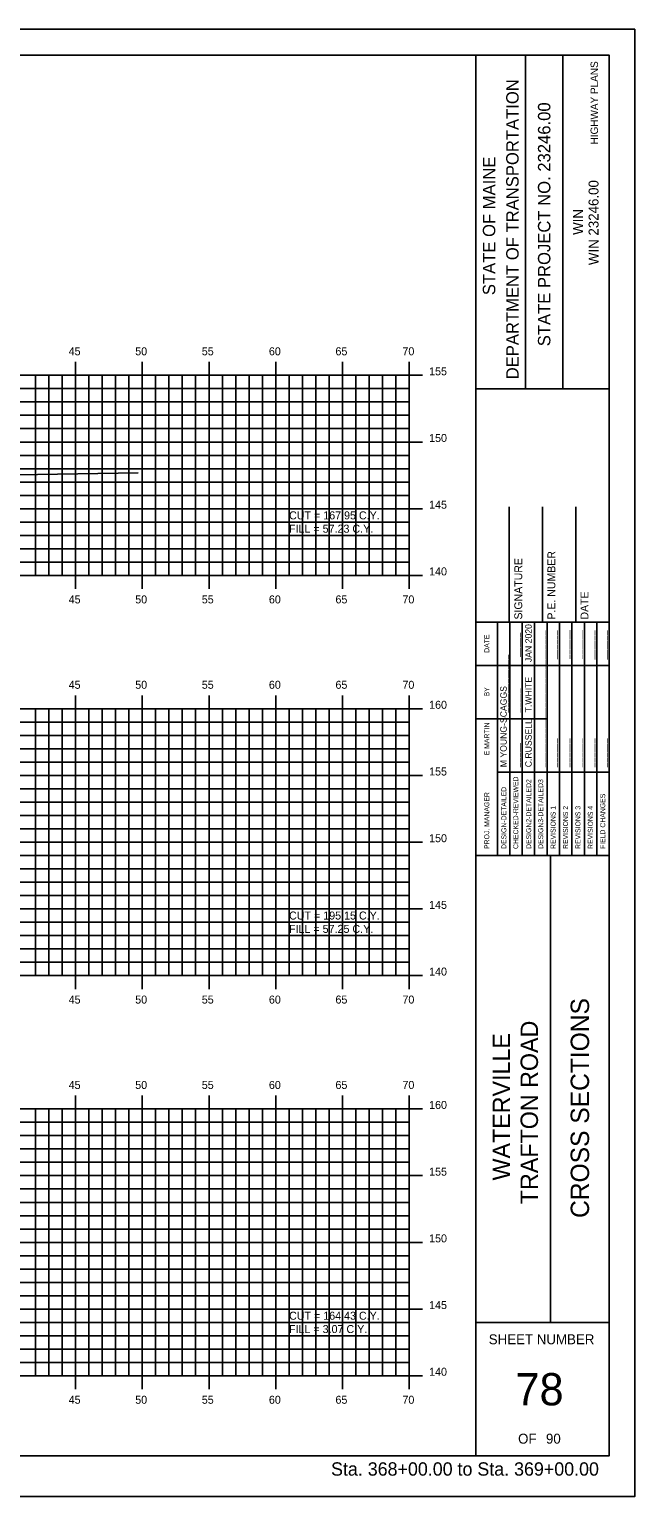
# Model space of a CAD drawing. Extents: x 1147855 to 1148025, y 608981 to 609091.
# Drawn here: x 1147979.7 to 1148025.1, y 608981.3 to 609091.3 of the extents above; entities that cross this region are included whole.
import ezdxf

# ---------------------------------------------------------------- set-up
doc = ezdxf.new("R2010")
doc.units = 0
for name, color, linetype in [('BORDER', 7, 'Continuous'), ('D_Text_Standard', 7, 'Continuous'), ('H_V ANNOTATION', 7, 'Continuous'), ('HIGHWAY_TITLE', 7, 'Continuous'), ('MAJOR', 7, 'Continuous'), ('MINOR', 7, 'Continuous'), ('PLOT BOUNDARY', 7, 'Continuous'), ('S_Roadway_Centerline', 7, 'Continuous')]:
    doc.layers.add(name, color=color, linetype=linetype)

msp = doc.modelspace()

# ---------------------------------------------------------------- linework, layer by layer
at = {"layer": 'BORDER'}
for p, q in [((1148013.21, 608984.34), (1148013.21, 609089.34)), ((1148016.94, 609064.33), (1148016.94, 609089.33)), ((1148019.73, 609064.33), (1148019.73, 609089.33)), ((1148013.21, 609064.33), (1148023.21, 609064.33)), ((1148015.71, 609046.84), (1148015.71, 609055.49)), ((1148018.21, 609046.84), (1148018.21, 609055.49)), ((1148020.71, 609046.84), (1148020.71, 609055.49)), ((1148013.21, 609046.84), (1148023.21, 609046.84)), ((1148013.21, 609029.34), (1148023.21, 609029.34)), ((1148018.8, 608994.34), (1148018.8, 609029.34)), ((1148013.21, 608994.34), (1148023.21, 608994.34))]:
    msp.add_line(p, q, dxfattribs=at)
msp.add_lwpolyline([(1147863.21, 608984.34), (1148023.21, 608984.34), (1148023.21, 609089.34), (1147863.21, 609089.34)], close=True, dxfattribs=at)
for points in [[(1148014.83, 609043.59), (1148014.83, 609046.84)], [(1148014.83, 609029.34), (1148014.83, 609046.13)], [(1148015.76, 609029.34), (1148015.76, 609046.84)], [(1148016.69, 609046.84), (1148016.69, 609029.34)], [(1148017.62, 609029.34), (1148017.62, 609046.84)], [(1148018.55, 609029.34), (1148018.55, 609046.84)], [(1148019.48, 609029.34), (1148019.48, 609046.84)], [(1148020.42, 609029.34), (1148020.42, 609046.84)], [(1148021.35, 609029.34), (1148021.35, 609046.84)], [(1148022.28, 609029.34), (1148022.28, 609046.84)], [(1148013.21, 609043.59), (1148023.21, 609043.59)], [(1148013.21, 609039.59), (1148014.83, 609039.59)], [(1148014.83, 609039.59), (1148018.55, 609039.59)], [(1148014.83, 609035.59), (1148023.21, 609035.59)]]:
    msp.add_lwpolyline(points, dxfattribs=at)
at = {"layer": 'MAJOR'}
for p, q in [((1147983.21, 609066.34), (1147983.21, 609065.34)), ((1147988.21, 609066.34), (1147988.21, 609065.34)), ((1147993.21, 609066.34), (1147993.21, 609065.34)), ((1147998.21, 609066.34), (1147998.21, 609065.34)), ((1148003.21, 609066.34), (1148003.21, 609065.34)), ((1148008.21, 609066.34), (1148008.21, 609065.34)), ((1147868.21, 609065.34), (1148008.21, 609065.34)), ((1147868.21, 609065.34), (1148008.21, 609065.34)), ((1147983.21, 609050.34), (1147983.21, 609065.34)), ((1147988.21, 609050.34), (1147988.21, 609065.34)), ((1147993.21, 609050.34), (1147993.21, 609065.34)), ((1147998.21, 609050.34), (1147998.21, 609065.34)), ((1148003.21, 609050.34), (1148003.21, 609065.34)), ((1148009.21, 609065.34), (1148007.21, 609065.34)), ((1148008.21, 609050.34), (1148008.21, 609065.34)), ((1148008.21, 609050.34), (1148008.21, 609065.34)), ((1147868.21, 609060.34), (1148008.21, 609060.34)), ((1148009.21, 609060.34), (1148007.21, 609060.34)), ((1147868.21, 609055.34), (1148008.21, 609055.34)), ((1148009.21, 609055.34), (1148007.21, 609055.34)), ((1147868.21, 609050.34), (1148008.21, 609050.34)), ((1147868.21, 609050.34), (1148008.21, 609050.34)), ((1147983.21, 609049.33), (1147983.21, 609050.34)), ((1147988.21, 609049.33), (1147988.21, 609050.34)), ((1147993.21, 609049.33), (1147993.21, 609050.34)), ((1147998.21, 609049.33), (1147998.21, 609050.34)), ((1148003.21, 609049.33), (1148003.21, 609050.34)), ((1148009.21, 609050.34), (1148007.21, 609050.34)), ((1148008.21, 609049.33), (1148008.21, 609050.34)), ((1147868.21, 609040.34), (1148008.21, 609040.34)), ((1147868.21, 609040.34), (1148008.21, 609040.34)), ((1147983.21, 609041.34), (1147983.21, 609040.34)), ((1147983.21, 609020.34), (1147983.21, 609040.34)), ((1147988.21, 609041.34), (1147988.21, 609040.34)), ((1147988.21, 609020.34), (1147988.21, 609040.34)), ((1147993.21, 609041.34), (1147993.21, 609040.34)), ((1147993.21, 609020.34), (1147993.21, 609040.34)), ((1147998.21, 609041.34), (1147998.21, 609040.34)), ((1147998.21, 609020.34), (1147998.21, 609040.34)), ((1148003.21, 609041.34), (1148003.21, 609040.34)), ((1148003.21, 609020.34), (1148003.21, 609040.34)), ((1148009.21, 609040.34), (1148007.21, 609040.34)), ((1148008.21, 609041.34), (1148008.21, 609040.34)), ((1148008.21, 609020.34), (1148008.21, 609040.34)), ((1148008.21, 609020.34), (1148008.21, 609040.34)), ((1147868.21, 609035.34), (1148008.21, 609035.34)), ((1148009.21, 609035.34), (1148007.21, 609035.34)), ((1147868.21, 609030.34), (1148008.21, 609030.34)), ((1148009.21, 609030.34), (1148007.21, 609030.34)), ((1147868.21, 609025.34), (1148008.21, 609025.34)), ((1148009.21, 609025.34), (1148007.21, 609025.34)), ((1147868.21, 609020.34), (1148008.21, 609020.34)), ((1147868.21, 609020.34), (1148008.21, 609020.34)), ((1147983.21, 609019.33), (1147983.21, 609020.34)), ((1147988.21, 609019.33), (1147988.21, 609020.34)), ((1147993.21, 609019.33), (1147993.21, 609020.34)), ((1147998.21, 609019.33), (1147998.21, 609020.34)), ((1148003.21, 609019.33), (1148003.21, 609020.34)), ((1148009.21, 609020.34), (1148007.21, 609020.34)), ((1148008.21, 609019.33), (1148008.21, 609020.34)), ((1147983.21, 609011.34), (1147983.21, 609010.34)), ((1147988.21, 609011.34), (1147988.21, 609010.34)), ((1147993.21, 609011.34), (1147993.21, 609010.34)), ((1147998.21, 609011.34), (1147998.21, 609010.34)), ((1148003.21, 609011.34), (1148003.21, 609010.34)), ((1148008.21, 609011.34), (1148008.21, 609010.34)), ((1147868.21, 609010.34), (1148008.21, 609010.34)), ((1147868.21, 609010.34), (1148008.21, 609010.34)), ((1147983.21, 608990.34), (1147983.21, 609010.34)), ((1147988.21, 608990.34), (1147988.21, 609010.34)), ((1147993.21, 608990.34), (1147993.21, 609010.34)), ((1147998.21, 608990.34), (1147998.21, 609010.34)), ((1148003.21, 608990.34), (1148003.21, 609010.34)), ((1148009.21, 609010.34), (1148007.21, 609010.34)), ((1148008.21, 608990.34), (1148008.21, 609010.34)), ((1148008.21, 608990.34), (1148008.21, 609010.34)), ((1147868.21, 609005.34), (1148008.21, 609005.34)), ((1148009.21, 609005.34), (1148007.21, 609005.34)), ((1147868.21, 609000.34), (1148008.21, 609000.34)), ((1148009.21, 609000.34), (1148007.21, 609000.34)), ((1147868.21, 608995.34), (1148008.21, 608995.34)), ((1148009.21, 608995.34), (1148007.21, 608995.34)), ((1147868.21, 608990.34), (1148008.21, 608990.34)), ((1147868.21, 608990.34), (1148008.21, 608990.34)), ((1147983.21, 608989.33), (1147983.21, 608990.34)), ((1147988.21, 608989.33), (1147988.21, 608990.34)), ((1147993.21, 608989.33), (1147993.21, 608990.34)), ((1147998.21, 608989.33), (1147998.21, 608990.34)), ((1148003.21, 608989.33), (1148003.21, 608990.34)), ((1148009.21, 608990.34), (1148007.21, 608990.34)), ((1148008.21, 608989.33), (1148008.21, 608990.34))]:
    msp.add_line(p, q, dxfattribs=at)
at = {"layer": 'MINOR'}
for p, q in [((1147980.21, 609050.34), (1147980.21, 609065.34)), ((1147981.21, 609050.34), (1147981.21, 609065.34)), ((1147982.21, 609050.34), (1147982.21, 609065.34)), ((1147984.21, 609050.34), (1147984.21, 609065.34)), ((1147985.21, 609050.34), (1147985.21, 609065.34)), ((1147986.21, 609050.34), (1147986.21, 609065.34)), ((1147987.21, 609050.34), (1147987.21, 609065.34)), ((1147989.21, 609050.34), (1147989.21, 609065.34)), ((1147990.21, 609050.34), (1147990.21, 609065.34)), ((1147991.21, 609050.34), (1147991.21, 609065.34)), ((1147992.21, 609050.34), (1147992.21, 609065.34)), ((1147994.21, 609050.34), (1147994.21, 609065.34)), ((1147995.21, 609050.34), (1147995.21, 609065.34)), ((1147996.21, 609050.34), (1147996.21, 609065.34)), ((1147997.21, 609050.34), (1147997.21, 609065.34)), ((1147999.21, 609050.34), (1147999.21, 609065.34)), ((1148000.21, 609050.34), (1148000.21, 609065.34)), ((1148001.21, 609050.34), (1148001.21, 609065.34)), ((1148002.21, 609050.34), (1148002.21, 609065.34)), ((1148004.21, 609050.34), (1148004.21, 609065.34)), ((1148005.21, 609050.34), (1148005.21, 609065.34)), ((1148006.21, 609050.34), (1148006.21, 609065.34)), ((1148007.21, 609050.34), (1148007.21, 609065.34)), ((1147868.21, 609064.34), (1148008.21, 609064.34)), ((1148008.21, 609064.34), (1148007.21, 609064.34)), ((1147868.21, 609063.34), (1148008.21, 609063.34)), ((1147868.21, 609062.34), (1148008.21, 609062.34)), ((1148008.21, 609063.34), (1148007.21, 609063.34)), ((1148008.21, 609062.34), (1148007.21, 609062.34)), ((1147868.21, 609061.34), (1148008.21, 609061.34)), ((1148008.21, 609061.34), (1148007.21, 609061.34)), ((1147868.21, 609059.34), (1148008.21, 609059.34)), ((1148008.21, 609059.34), (1148007.21, 609059.34)), ((1147868.21, 609058.34), (1148008.21, 609058.34)), ((1148008.21, 609058.34), (1148007.21, 609058.34)), ((1147868.21, 609057.34), (1148008.21, 609057.34)), ((1148008.21, 609057.34), (1148007.21, 609057.34)), ((1147868.21, 609056.34), (1148008.21, 609056.34)), ((1148008.21, 609056.34), (1148007.21, 609056.34)), ((1147868.21, 609054.34), (1148008.21, 609054.34)), ((1148008.21, 609054.34), (1148007.21, 609054.34)), ((1147868.21, 609053.34), (1148008.21, 609053.34)), ((1148008.21, 609053.34), (1148007.21, 609053.34)), ((1147868.21, 609052.34), (1148008.21, 609052.34)), ((1147868.21, 609051.34), (1148008.21, 609051.34)), ((1148008.21, 609052.34), (1148007.21, 609052.34)), ((1148008.21, 609051.34), (1148007.21, 609051.34)), ((1147980.21, 609020.34), (1147980.21, 609040.34)), ((1147981.21, 609020.34), (1147981.21, 609040.34)), ((1147982.21, 609020.34), (1147982.21, 609040.34)), ((1147984.21, 609020.34), (1147984.21, 609040.34)), ((1147985.21, 609020.34), (1147985.21, 609040.34)), ((1147986.21, 609020.34), (1147986.21, 609040.34)), ((1147987.21, 609020.34), (1147987.21, 609040.34)), ((1147989.21, 609020.34), (1147989.21, 609040.34)), ((1147990.21, 609020.34), (1147990.21, 609040.34)), ((1147991.21, 609020.34), (1147991.21, 609040.34)), ((1147992.21, 609020.34), (1147992.21, 609040.34)), ((1147994.21, 609020.34), (1147994.21, 609040.34)), ((1147995.21, 609020.34), (1147995.21, 609040.34)), ((1147996.21, 609020.34), (1147996.21, 609040.34)), ((1147997.21, 609020.34), (1147997.21, 609040.34)), ((1147999.21, 609020.34), (1147999.21, 609040.34)), ((1148000.21, 609020.34), (1148000.21, 609040.34)), ((1148001.21, 609020.34), (1148001.21, 609040.34)), ((1148002.21, 609020.34), (1148002.21, 609040.34)), ((1148004.21, 609020.34), (1148004.21, 609040.34)), ((1148005.21, 609020.34), (1148005.21, 609040.34)), ((1148006.21, 609020.34), (1148006.21, 609040.34)), ((1148007.21, 609020.34), (1148007.21, 609040.34)), ((1147868.21, 609039.34), (1148008.21, 609039.34)), ((1148008.21, 609039.34), (1148007.21, 609039.34)), ((1147868.21, 609038.34), (1148008.21, 609038.34)), ((1148008.21, 609038.34), (1148007.21, 609038.34)), ((1147868.21, 609037.34), (1148008.21, 609037.34)), ((1148008.21, 609037.34), (1148007.21, 609037.34)), ((1147868.21, 609036.34), (1148008.21, 609036.34)), ((1148008.21, 609036.34), (1148007.21, 609036.34)), ((1147868.21, 609034.34), (1148008.21, 609034.34)), ((1148008.21, 609034.34), (1148007.21, 609034.34)), ((1147868.21, 609033.34), (1148008.21, 609033.34)), ((1148008.21, 609033.34), (1148007.21, 609033.34)), ((1147868.21, 609032.34), (1148008.21, 609032.34)), ((1148008.21, 609032.34), (1148007.21, 609032.34)), ((1147868.21, 609031.34), (1148008.21, 609031.34)), ((1148008.21, 609031.34), (1148007.21, 609031.34)), ((1147868.21, 609029.34), (1148008.21, 609029.34)), ((1148008.21, 609029.34), (1148007.21, 609029.34)), ((1147868.21, 609028.34), (1148008.21, 609028.34)), ((1148008.21, 609028.34), (1148007.21, 609028.34)), ((1147868.21, 609027.34), (1148008.21, 609027.34)), ((1148008.21, 609027.34), (1148007.21, 609027.34)), ((1147868.21, 609026.34), (1148008.21, 609026.34)), ((1148008.21, 609026.34), (1148007.21, 609026.34)), ((1147868.21, 609024.34), (1148008.21, 609024.34)), ((1148008.21, 609024.34), (1148007.21, 609024.34)), ((1147868.21, 609023.34), (1148008.21, 609023.34)), ((1148008.21, 609023.34), (1148007.21, 609023.34)), ((1147868.21, 609022.34), (1148008.21, 609022.34)), ((1148008.21, 609022.34), (1148007.21, 609022.34)), ((1147868.21, 609021.34), (1148008.21, 609021.34)), ((1148008.21, 609021.34), (1148007.21, 609021.34)), ((1147980.21, 608990.34), (1147980.21, 609010.34)), ((1147981.21, 608990.34), (1147981.21, 609010.34)), ((1147982.21, 608990.34), (1147982.21, 609010.34)), ((1147984.21, 608990.34), (1147984.21, 609010.34)), ((1147985.21, 608990.34), (1147985.21, 609010.34)), ((1147986.21, 608990.34), (1147986.21, 609010.34)), ((1147987.21, 608990.34), (1147987.21, 609010.34)), ((1147989.21, 608990.34), (1147989.21, 609010.34)), ((1147990.21, 608990.34), (1147990.21, 609010.34)), ((1147991.21, 608990.34), (1147991.21, 609010.34)), ((1147992.21, 608990.34), (1147992.21, 609010.34)), ((1147994.21, 608990.34), (1147994.21, 609010.34)), ((1147995.21, 608990.34), (1147995.21, 609010.34)), ((1147996.21, 608990.34), (1147996.21, 609010.34)), ((1147997.21, 608990.34), (1147997.21, 609010.34)), ((1147999.21, 608990.34), (1147999.21, 609010.34)), ((1148000.21, 608990.34), (1148000.21, 609010.34)), ((1148001.21, 608990.34), (1148001.21, 609010.34)), ((1148002.21, 608990.34), (1148002.21, 609010.34)), ((1148004.21, 608990.34), (1148004.21, 609010.34)), ((1148005.21, 608990.34), (1148005.21, 609010.34)), ((1148006.21, 608990.34), (1148006.21, 609010.34)), ((1148007.21, 608990.34), (1148007.21, 609010.34)), ((1147868.21, 609009.34), (1148008.21, 609009.34)), ((1148008.21, 609009.34), (1148007.21, 609009.34)), ((1147868.21, 609008.34), (1148008.21, 609008.34)), ((1147868.21, 609007.34), (1148008.21, 609007.34)), ((1148008.21, 609008.34), (1148007.21, 609008.34)), ((1148008.21, 609007.34), (1148007.21, 609007.34)), ((1147868.21, 609006.34), (1148008.21, 609006.34)), ((1148008.21, 609006.34), (1148007.21, 609006.34)), ((1147868.21, 609004.34), (1148008.21, 609004.34)), ((1148008.21, 609004.34), (1148007.21, 609004.34)), ((1147868.21, 609003.34), (1148008.21, 609003.34)), ((1148008.21, 609003.34), (1148007.21, 609003.34)), ((1147868.21, 609002.34), (1148008.21, 609002.34)), ((1148008.21, 609002.34), (1148007.21, 609002.34)), ((1147868.21, 609001.34), (1148008.21, 609001.34)), ((1148008.21, 609001.34), (1148007.21, 609001.34)), ((1147868.21, 608999.34), (1148008.21, 608999.34)), ((1148008.21, 608999.34), (1148007.21, 608999.34)), ((1147868.21, 608998.34), (1148008.21, 608998.34)), ((1148008.21, 608998.34), (1148007.21, 608998.34)), ((1147868.21, 608997.34), (1148008.21, 608997.34)), ((1147868.21, 608996.34), (1148008.21, 608996.34)), ((1148008.21, 608997.34), (1148007.21, 608997.34)), ((1148008.21, 608996.34), (1148007.21, 608996.34)), ((1147868.21, 608994.34), (1148008.21, 608994.34)), ((1148008.21, 608994.34), (1148007.21, 608994.34)), ((1147868.21, 608993.34), (1148008.21, 608993.34)), ((1148008.21, 608993.34), (1148007.21, 608993.34)), ((1147868.21, 608992.34), (1148008.21, 608992.34)), ((1148008.21, 608992.34), (1148007.21, 608992.34)), ((1147868.21, 608991.34), (1148008.21, 608991.34)), ((1148008.21, 608991.34), (1148007.21, 608991.34))]:
    msp.add_line(p, q, dxfattribs=at)
at = {"layer": 'PLOT BOUNDARY'}
msp.add_lwpolyline([(1147855.12, 608981.28), (1148025.12, 608981.28), (1148025.12, 609091.28), (1147855.12, 609091.28)], close=True, dxfattribs=at)
at = {"layer": 'S_Roadway_Centerline'}
msp.add_lwpolyline([(1147876.63, 609059.22), (1147887.18, 609058.99), (1147889.24, 609058.9), (1147892.86, 609058.82), (1147909.28, 609058.76), (1147913.24, 609058.76), (1147913.61, 609058.68), (1147919.45, 609057.08), (1147921.46, 609057.25), (1147923.17, 609057.54), (1147925.19, 609057.7), (1147926.36, 609057.78), (1147928.34, 609057.8), (1147938.46, 609057.93), (1147944.06, 609057.8), (1147958.4, 609057.48), (1147959.91, 609057.57), (1147961.81, 609057.57), (1147963.81, 609057.67), (1147966.88, 609057.69), (1147971.68, 609057.89), (1147974.78, 609057.9), (1147977.3, 609057.85), (1147987.9, 609058.02)], dxfattribs=at)

# ---------------------------------------------------------------- texts
at = {"layer": 'BORDER'}
for s, height, p in [('DEPARTMENT OF TRANSPORTATION', 0.9318, (1148016.42, 609065.04)), ('STATE PROJECT NO. 23246.00', 0.9318, (1148018.8, 609067.52)), ('STATE OF MAINE', 0.9318, (1148014.67, 609071.35)), ('WIN 23246.00', 0.7453, (1148022.41, 609073.6)), ('WIN', 0.745, (1148021.25, 609075.87)), ('SIGNATURE', 0.591, (1148016.69, 609047.03)), ('P.E. NUMBER', 0.5906, (1148019.17, 609047.03)), ('DATE', 0.591, (1148021.65, 609047.03)), ('DATE', 0.371, (1148014.22, 609044.54)), ('_____', 0.485, (1148016.43, 609044.24)), ('JAN 2020', 0.485, (1148017.4, 609043.84)), ('______', 0.485, (1148018.29, 609044.06)), ('______', 0.485, (1148019.22, 609044.06)), ('______', 0.485, (1148020.15, 609044.07)), ('______', 0.485, (1148021.09, 609044.07)), ('______', 0.485, (1148022.02, 609044.04)), ('______', 0.485, (1148022.95, 609044.04)), ('____________', 0.4845, (1148015.53, 609040.07)), ('____________', 0.4845, (1148018.29, 609040.07)), ('T.WHITE', 0.485, (1148017.4, 609040.07)), ('BY', 0.371, (1148014.22, 609041.27)), ('M YOUNG-SCAGGS', 0.4845, (1148015.53, 609035.96)), ('_____', 0.485, (1148016.47, 609040.07)), ('C.RUSSELL', 0.485, (1148017.4, 609035.96)), ('____________', 0.4845, (1148018.29, 609035.96)), ('E MARTIN', 0.373, (1148014.22, 609036.85)), ('______', 0.485, (1148019.22, 609035.96)), ('______', 0.485, (1148020.15, 609035.96)), ('______', 0.485, (1148021.09, 609035.96)), ('______', 0.485, (1148022.02, 609035.96)), ('______', 0.485, (1148022.95, 609035.96)), ('_____', 0.485, (1148016.43, 609035.96)), ('CHECKED-REVIEWED', 0.3727, (1148016.39, 609029.83)), ('DESIGN2-DETAILED2', 0.3727, (1148017.36, 609029.83)), ('DESIGN3-DETAILED3', 0.3727, (1148018.26, 609029.83)), ('PROJ. MANAGER', 0.3727, (1148014.22, 609029.83)), ('DESIGN-DETAILED', 0.3727, (1148015.5, 609029.83)), ('FIELD CHANGES', 0.3727, (1148022.91, 609029.83)), ('REVISIONS 1', 0.3727, (1148019.19, 609029.83)), ('REVISIONS 2', 0.3727, (1148020.12, 609029.83)), ('REVISIONS 3', 0.3727, (1148021.05, 609029.83)), ('REVISIONS 4', 0.3727, (1148021.98, 609029.83)), ('CROSS SECTIONS', 1.3779, (1148021.7, 609002.17))]:
    msp.add_text(s, height=height, rotation=90, dxfattribs=at).set_placement(p)
for s, height, p in [('SHEET NUMBER', 0.7453, (1148014.18, 608992.7)), ('78', 2.419, (1148016.19, 608988.12)), ('OF', 0.745, (1148016.38, 608985.25)), ('90', 0.745, (1148018.47, 608985.25))]:
    msp.add_text(s, height=height, dxfattribs=at).set_placement(p)
at = {"layer": 'D_Text_Standard'}
for s, p in [('CUT = 167.95 C.Y.', (1147999.21, 609054.54)), ('FILL = 57.23 C.Y.', (1147999.21, 609053.54)), ('CUT = 195.15 C.Y.', (1147999.21, 609024.54)), ('FILL = 57.25 C.Y.', (1147999.21, 609023.54)), ('CUT = 164.43 C.Y.', (1147999.21, 608994.54)), ('FILL = 3.07 C.Y.', (1147999.21, 608993.54))]:
    msp.add_text(s, height=0.6, dxfattribs=at).set_placement(p)
at = {"layer": 'H_V ANNOTATION'}
for s, height, p in [('45', 0.6, (1147982.69, 609066.84)), ('50', 0.6, (1147987.68, 609066.84)), ('55', 0.6, (1147992.67, 609066.84)), ('60', 0.6, (1147997.7, 609066.84)), ('65', 0.6, (1148002.69, 609066.84)), ('70', 0.6, (1148007.71, 609066.84)), ('155', 0.6, (1148009.71, 609065.34)), ('150', 0.6, (1148009.71, 609060.34)), ('145', 0.6, (1148009.71, 609055.34)), ('140', 0.6, (1148009.71, 609050.34)), ('45', 0.6, (1147982.69, 609048.24)), ('50', 0.6, (1147987.68, 609048.24)), ('55', 0.6, (1147992.67, 609048.24)), ('60', 0.6, (1147997.7, 609048.24)), ('65', 0.6, (1148002.69, 609048.24)), ('70', 0.6, (1148007.71, 609048.24)), ('45', 0.6, (1147982.69, 609041.84)), ('50', 0.6, (1147987.68, 609041.84)), ('55', 0.6, (1147992.67, 609041.84)), ('60', 0.6, (1147997.7, 609041.84)), ('65', 0.6, (1148002.69, 609041.84)), ('70', 0.6, (1148007.71, 609041.84)), ('160', 0.6, (1148009.71, 609040.34)), ('155', 0.6, (1148009.71, 609035.34)), ('150', 0.6, (1148009.71, 609030.34)), ('145', 0.6, (1148009.71, 609025.34)), ('140', 0.6, (1148009.71, 609020.34)), ('45', 0.6, (1147982.69, 609018.24)), ('50', 0.6, (1147987.68, 609018.24)), ('55', 0.6, (1147992.67, 609018.24)), ('60', 0.6, (1147997.7, 609018.24)), ('65', 0.6, (1148002.69, 609018.24)), ('70', 0.6, (1148007.71, 609018.24)), ('45', 0.6, (1147982.69, 609011.84)), ('50', 0.6, (1147987.68, 609011.84)), ('55', 0.6, (1147992.67, 609011.84)), ('60', 0.6, (1147997.7, 609011.84)), ('65', 0.6, (1148002.69, 609011.84)), ('70', 0.6, (1148007.71, 609011.84)), ('160', 0.6, (1148009.71, 609010.34)), ('155', 0.6, (1148009.71, 609005.34)), ('150', 0.6, (1148009.71, 609000.34)), ('145', 0.6, (1148009.71, 608995.34)), ('140', 0.6, (1148009.71, 608990.34)), ('45', 0.6, (1147982.69, 608988.24)), ('50', 0.6, (1147987.68, 608988.24)), ('55', 0.6, (1147992.67, 608988.24)), ('60', 0.6, (1147997.7, 608988.24)), ('65', 0.6, (1148002.69, 608988.24)), ('70', 0.6, (1148007.71, 608988.24)), ('Sta. 368+00.00 to Sta. 369+00.00', 1.0002, (1148002.36, 608982.85))]:
    msp.add_text(s, height=height, dxfattribs=at).set_placement(p)
at = {"layer": 'HIGHWAY_TITLE'}
for s, height, p in [('HIGHWAY PLANS', 0.559, (1148022.37, 609082.65)), ('TRAFTON ROAD', 1.3043, (1148017.87, 609003.2)), ('WATERVILLE', 1.304, (1148015.78, 609004.98))]:
    msp.add_text(s, height=height, rotation=90, dxfattribs=at).set_placement(p)

doc.saveas('drawing.dxf')
